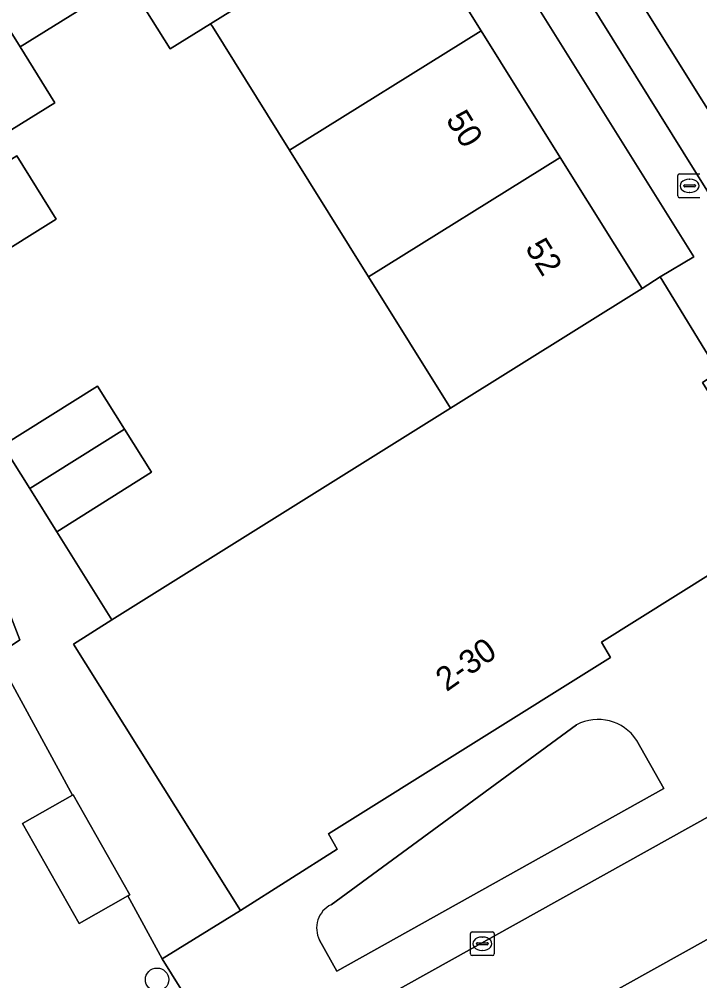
# Model space of a CAD drawing. Extents: x 159664 to 160323, y 385312 to 386115.
# Drawn here: x 159815.37 to 159843.96, y 385716.94 to 385757.34 of the extents above; entities that cross this region are included whole.
import ezdxf

# ---------------------------------------------------------------- set-up
doc = ezdxf.new("R2010")
doc.units = 0
for name, color, linetype in [('IMGEO_Boom', 7, 'Continuous'), ('IMGEO_Brandkraan', 7, 'Continuous'), ('IMGEO_Erf', 7, 'Continuous'), ('IMGEO_Groenvoorziening', 7, 'Continuous'), ('IMGEO_Kolk', 7, 'Continuous'), ('IMGEO_Pand', 7, 'Continuous'), ('IMGEO_Pand_nummerreeks', 7, 'Continuous'), ('IMGEO_Parkeervlak_open', 7, 'Continuous'), ('IMGEO_Rijbaan_lokaal_open', 7, 'Continuous'), ('IMGEO_Voetpad_open', 7, 'Continuous')]:
    doc.layers.add(name, color=color, linetype=linetype)

msp = doc.modelspace()

# ---------------------------------------------------------------- linework, layer by layer
at = {"layer": 'IMGEO_Boom'}
msp.add_circle((159821.156, 385716.99), 0.489, dxfattribs=at)
at = {"layer": 'IMGEO_Brandkraan'}
for p, q in [((159843.029, 385749.914), (159843.029, 385750.766)), ((159843.104, 385750.84), (159843.956, 385750.84)), ((159843.288, 385750.334), (159843.288, 385750.346)), ((159843.726, 385750.297), (159843.328, 385750.297)), ((159843.331, 385750.383), (159843.729, 385750.383)), ((159843.517, 385750.62), (159843.542, 385750.62)), ((159843.772, 385750.346), (159843.772, 385750.334)), ((159843.956, 385749.84), (159843.104, 385749.84)), ((159843.54, 385750.06), (159843.515, 385750.06))]:
    msp.add_line(p, q, dxfattribs=at)
for points in [[(159843.029, 385749.914), (159843.029, 385750.766)], [(159843.104, 385750.84), (159843.956, 385750.84)], [(159843.956, 385749.84), (159843.104, 385749.84)]]:
    msp.add_lwpolyline(points, dxfattribs=at)
for centre, radius, start, end in [((159843.106, 385750.764), 0.0765, 91.552, 178.448), ((159843.106, 385750.764), 0.0765, 91.552, 178.448), ((159843.328, 385750.343), 0.0403, 85.8775, 175.7526), ((159843.325, 385750.333), 0.0366, 178.938, 274.7102), ((159843.729, 385750.34), 0.043, 264.8664, 352.4533), ((159843.733, 385750.345), 0.0386, 1.7309, 96.639), ((159843.106, 385749.916), 0.0765, 181.552, 268.448), ((159843.106, 385749.916), 0.0765, 181.552, 268.448)]:
    msp.add_arc(centre, radius, start, end, dxfattribs=at)
for centre, major_axis, ratio, start_param, end_param in [((159843.516, 385750.34), (-0.387, 0.002), 0.722429, 4.712389, 7.853982), ((159843.541, 385750.34), (-0.39, 0.002), 0.717154, 1.570796, 4.712389)]:
    msp.add_ellipse(centre, major_axis=major_axis, ratio=ratio, start_param=start_param, end_param=end_param, dxfattribs=at)
at = {"layer": 'IMGEO_Erf'}
for points in [[(159830.13, 385769.11), (159827.963, 385767.758), (159831.457, 385762.161), (159834.773, 385756.848), (159838.09, 385751.534), (159841.531, 385746.024), (159842.287, 385746.516), (159843.706, 385747.354)], [(159830.036, 385746.522), (159826.72, 385751.836), (159823.479, 385757.029), (159823.404, 385757.149), (159821.707, 385756.093), (159819.895, 385758.985), (159815.411, 385756.178), (159816.859, 385753.82), (159810.035, 385749.593), (159809.719, 385747.405), (159811.745, 385744.284), (159813.611, 385744.153), (159813.959, 385743.68), (159813.218, 385741.755), (159814.676, 385739.428), (159818.659, 385741.923), (159819.793, 385740.114), (159820.927, 385738.304), (159816.944, 385735.809), (159819.262, 385732.102), (159833.484, 385740.995)], [(159816.912, 385748.936), (159814.058, 385747.164), (159812.407, 385749.823), (159815.261, 385751.595)]]:
    msp.add_lwpolyline(points, close=True, dxfattribs=at)
msp.add_lwpolyline([(159801.328, 385702.097), (159823.466, 385714.495), (159821.37, 385717.867), (159819.925, 385720.508), (159817.884, 385719.351), (159815.506, 385723.543), (159817.611, 385724.737), (159814.397, 385730.611), (159815.386, 385731.262), (159812.661, 385738.343)], dxfattribs=at)
at = {"layer": 'IMGEO_Groenvoorziening'}
for points in [[(159838.78, 385727.694), (159828.472, 385720.137)], [(159827.986, 385718.649), (159828.708, 385717.352), (159842.446, 385725.022), (159841.298, 385727.055)]]:
    msp.add_lwpolyline(points, dxfattribs=at)
for centre, radius, start, end in [((159839.687, 385725.987), 1.933, 33.544, 117.977), ((159828.942, 385719.16), 1.084, 115.6971, 208.1275)]:
    msp.add_arc(centre, radius, start, end, dxfattribs=at)
at = {"layer": 'IMGEO_Kolk'}
for p, q in [((159834.322, 385718.073), (159834.322, 385718.925)), ((159834.397, 385718.999), (159835.249, 385718.999)), ((159834.81, 385718.779), (159834.835, 385718.779)), ((159835.323, 385718.925), (159835.323, 385718.073)), ((159834.581, 385718.493), (159834.581, 385718.505)), ((159835.019, 385718.456), (159834.621, 385718.456)), ((159834.624, 385718.542), (159835.022, 385718.542)), ((159835.065, 385718.505), (159835.065, 385718.493)), ((159835.249, 385717.999), (159834.397, 385717.999)), ((159834.833, 385718.219), (159834.808, 385718.219))]:
    msp.add_line(p, q, dxfattribs=at)
for points in [[(159834.322, 385718.073), (159834.322, 385718.925)], [(159834.397, 385718.999), (159835.249, 385718.999)], [(159835.323, 385718.925), (159835.323, 385718.073)], [(159835.249, 385717.999), (159834.397, 385717.999)]]:
    msp.add_lwpolyline(points, dxfattribs=at)
for centre, radius, start, end in [((159834.399, 385718.923), 0.0765, 91.552, 178.448), ((159834.399, 385718.923), 0.0765, 91.552, 178.448), ((159835.247, 385718.923), 0.0765, 1.552, 88.448), ((159835.247, 385718.923), 0.0765, 1.552, 88.448), ((159834.621, 385718.502), 0.0403, 85.8775, 175.7526), ((159834.618, 385718.492), 0.0366, 178.938, 274.7102), ((159835.022, 385718.499), 0.043, 264.8664, 352.4533), ((159835.026, 385718.504), 0.0386, 1.7309, 96.639), ((159834.399, 385718.075), 0.0765, 181.552, 268.448), ((159834.399, 385718.075), 0.0765, 181.552, 268.448), ((159835.247, 385718.075), 0.0765, 271.552, 358.448), ((159835.247, 385718.075), 0.0765, 271.552, 358.448)]:
    msp.add_arc(centre, radius, start, end, dxfattribs=at)
for centre, major_axis, ratio, start_param, end_param in [((159834.809, 385718.499), (-0.387, 0.002), 0.722429, 4.712389, 7.853982), ((159834.834, 385718.499), (-0.39, 0.002), 0.717154, 1.570796, 4.712389)]:
    msp.add_ellipse(centre, major_axis=major_axis, ratio=ratio, start_param=start_param, end_param=end_param, dxfattribs=at)
at = {"layer": 'IMGEO_Pand'}
for points in [[(159831.457, 385762.161), (159827.963, 385767.758), (159813.729, 385758.865), (159815.411, 385756.178), (159819.895, 385758.985), (159821.707, 385756.093), (159823.404, 385757.149)], [(159831.457, 385762.161), (159823.404, 385757.149), (159823.479, 385757.029), (159826.72, 385751.836), (159834.773, 385756.848)], [(159826.72, 385751.836), (159830.036, 385746.522), (159838.09, 385751.534), (159834.773, 385756.848)], [(159816.912, 385748.936), (159815.261, 385751.595), (159812.407, 385749.823), (159814.058, 385747.164)], [(159841.531, 385746.024), (159838.09, 385751.534), (159830.036, 385746.522), (159833.484, 385740.995)], [(159847.768, 385736.144), (159844.077, 385742.073), (159844.746, 385742.506), (159842.287, 385746.516), (159841.531, 385746.024), (159833.484, 385740.995), (159819.262, 385732.102), (159817.643, 385731.089), (159824.657, 385719.9), (159828.726, 385722.478), (159828.359, 385723.117), (159840.202, 385730.528), (159839.831, 385731.166)], [(159818.659, 385741.923), (159814.676, 385739.428), (159815.81, 385737.618), (159819.793, 385740.114)], [(159816.944, 385735.809), (159820.927, 385738.304), (159819.793, 385740.114), (159815.81, 385737.618)], [(159817.611, 385724.737), (159815.506, 385723.543), (159817.884, 385719.351), (159819.925, 385720.508), (159820.012, 385720.558), (159817.634, 385724.75)]]:
    msp.add_lwpolyline(points, close=True, dxfattribs=at)
at = {"layer": 'IMGEO_Parkeervlak_open'}
for points in [[(159741.034, 385915.456), (159751.377, 385898.907), (159753.743, 385895.078), (159790.443, 385836.375), (159792.83, 385832.57), (159829.402, 385773.998), (159831.787, 385770.18), (159850.746, 385739.72), (159852.33, 385740.71), (159841.328, 385758.304), (159807.874, 385811.971), (159785.139, 385848.258)], [(159852.229, 385723.11), (159836.373, 385714.273)]]:
    msp.add_lwpolyline(points, dxfattribs=at)
at = {"layer": 'IMGEO_Rijbaan_lokaal_open'}
for points in [[(159847.352, 385757.199), (159845.062, 385760.744), (159841.328, 385758.304), (159852.33, 385740.71), (159853.294, 385739.117), (159857.224, 385741.538), (159855.349, 385744.522)], [(159852.75, 385728.539), (159828.906, 385715.245), (159823.5, 385712.196), (159802.203, 385700.317)], [(159813.27, 385701.345), (159813.337, 385701.382), (159831.63, 385711.577), (159836.373, 385714.273), (159852.229, 385723.11)]]:
    msp.add_lwpolyline(points, dxfattribs=at)
at = {"layer": 'IMGEO_Voetpad_open'}
for points in [[(159830.13, 385769.11), (159843.706, 385747.354), (159842.287, 385746.516), (159844.746, 385742.506), (159844.077, 385742.073), (159847.768, 385736.144), (159853.294, 385739.117), (159852.33, 385740.71), (159850.746, 385739.72), (159831.787, 385770.18)], [(159810.035, 385749.593), (159816.859, 385753.82), (159815.411, 385756.178), (159813.729, 385758.865)], [(159812.661, 385738.343), (159815.386, 385731.262), (159814.397, 385730.611), (159817.611, 385724.737), (159817.634, 385724.75), (159820.012, 385720.558), (159819.925, 385720.508), (159821.37, 385717.867), (159824.657, 385719.9), (159817.643, 385731.089), (159819.262, 385732.102), (159816.944, 385735.809), (159815.81, 385737.618), (159814.676, 385739.428)], [(159855.019, 385736.497), (159854.703, 385736.986), (159854.319, 385737.464), (159853.294, 385739.117), (159847.768, 385736.144), (159839.831, 385731.166), (159840.202, 385730.528), (159828.359, 385723.117), (159828.726, 385722.478), (159824.657, 385719.9), (159821.37, 385717.867), (159823.466, 385714.495), (159801.328, 385702.097), (159802.203, 385700.317), (159823.5, 385712.196)], [(159823.5, 385712.196), (159822.963, 385713.117), (159828.366, 385716.165), (159828.906, 385715.245), (159852.75, 385728.539)], [(159828.472, 385720.137), (159838.78, 385727.694)], [(159841.298, 385727.055), (159842.446, 385725.022), (159828.708, 385717.352), (159827.986, 385718.649)]]:
    msp.add_lwpolyline(points, dxfattribs=at)
for centre, radius, start, end in [((159839.687, 385725.987), 1.933, 33.544, 117.977), ((159828.942, 385719.16), 1.084, 115.6971, 208.1275)]:
    msp.add_arc(centre, radius, start, end, dxfattribs=at)

# ---------------------------------------------------------------- texts
at = {"layer": 'IMGEO_Pand_nummerreeks'}
for s, rotation, p in [('50', 301.755, (159833.265, 385753.12)), ('52', 301.755, (159836.596, 385747.738)), ('2-30', 35.0937, (159833.317, 385729.063))]:
    msp.add_text(s, height=1, rotation=rotation, dxfattribs=at).set_placement(p)

doc.saveas('drawing.dxf')
